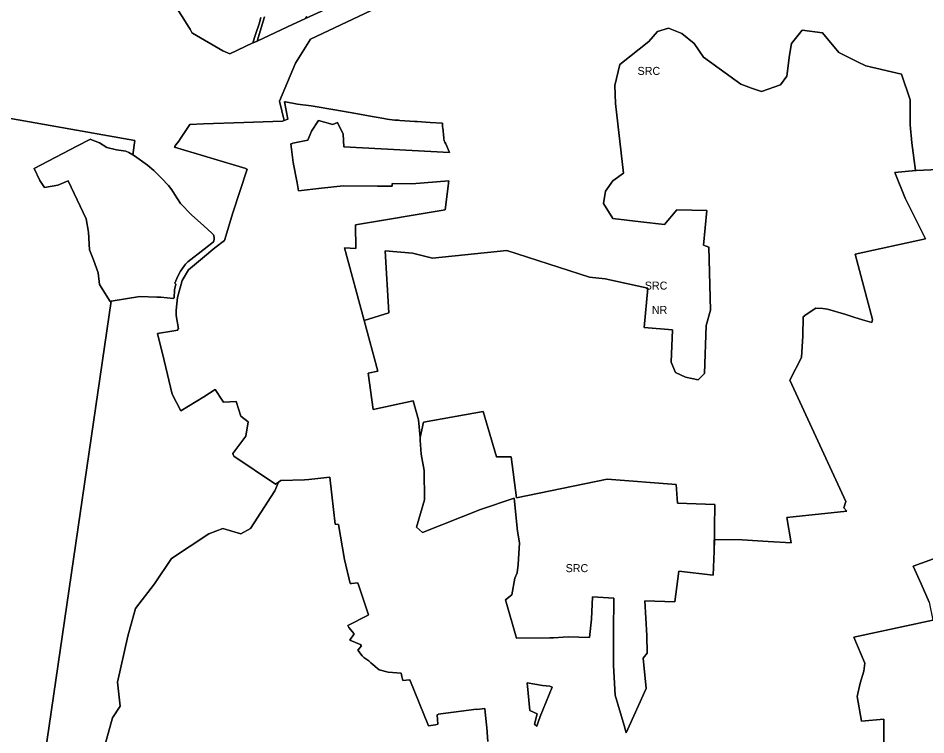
# Model space of a CAD drawing. Extents: x 598968 to 613553, y 4409678 to 4430833.
# Drawn here: x 605292 to 606653, y 4414204 to 4415278 of the extents above; entities that cross this region are included whole.
import ezdxf

# ---------------------------------------------------------------- set-up
doc = ezdxf.new("R2010")
doc.units = 0
for name, color, linetype in [('1', 7, 'Continuous'), ('Nucli Rural', 7, 'Continuous'), ('Sòl Rústic Comú', 7, 'Continuous')]:
    doc.layers.add(name, color=color, linetype=linetype)

msp = doc.modelspace()

# ---------------------------------------------------------------- linework, layer by layer
at = {"layer": '1'}
for points in [[(605525.6972, 4415299.6089), (605547.7802, 4415264.6209), (605549.5351, 4415261.4135), (605552.5806, 4415255.6474), (605553.1532, 4415255.3186), (605598.7444, 4415229.1359), (605609.1856, 4415224.6552), (605643.5975, 4415240.7757), (605643.8664, 4415240.9011), (605643.8703, 4415240.9026), (605647.8489, 4415253.402), (605649.7389, 4415259.3394), (605651.5659, 4415265.0792), (605653.0331, 4415269.498), (605655.7911, 4415279.0062)], [(605661.1567, 4415279.7497), (605649.9412, 4415243.7057), (605649.9455, 4415243.7077), (605695.5427, 4415264.7584), (605722.5347, 4415277.5027), (605724.6022, 4415280.4167)], [(605724.6022, 4415280.4167), (605722.5347, 4415277.5027), (605722.6392, 4415277.2668), (605752.1398, 4415290.8862)], [(605655.7911, 4415279.0062), (605653.0331, 4415269.498), (605651.5659, 4415265.0792), (605649.7389, 4415259.3394), (605647.8489, 4415253.402), (605643.8703, 4415240.9026), (605643.8744, 4415240.9036), (605649.9412, 4415243.7057), (605661.1567, 4415279.7497)]]:
    msp.add_lwpolyline(points, dxfattribs=at)
for points in [[(605463.4611, 4415073.426), (605457.6411, 4415076.8972), (605453.0401, 4415078.5902), (605439.3201, 4415080.8702), (605424.8201, 4415084.3902), (605413.9101, 4415091.2402), (605400.9731, 4415096.0988), (605400.0191, 4415096.4572), (605379.7631, 4415086.0116), (605315.6501, 4415052.9502), (605324.1501, 4415034.7302), (605331.2801, 4415024.2702), (605351.2001, 4415027.8102), (605366.7701, 4415034.3302), (605393.6601, 4414977.2102), (605397.0701, 4414957.3602), (605398.9701, 4414931.0202), (605404.9301, 4414916.0202), (605411.8401, 4414896.2502), (605413.8501, 4414879.0402), (605429.6851, 4414853.6892), (605431.4065, 4414853.9728), (605474.1001, 4414861.0102), (605499.7201, 4414860.0402), (605505.6601, 4414859.9602), (605524.9001, 4414857.9902), (605525.6501, 4414859.2302), (605526.1301, 4414871.0602), (605528.2501, 4414879.4502), (605526.6801, 4414880.7902), (605531.1501, 4414891.5802), (605535.3801, 4414898.9402), (605542.6701, 4414909.3802), (605546.2101, 4414913.0202), (605570.5901, 4414931.9702), (605584.4601, 4414943.0702), (605585.7501, 4414946.4102), (605585.6701, 4414950.0002), (605584.4301, 4414953.5302), (605582.1801, 4414956.1202), (605570.3701, 4414966.6202), (605551.8301, 4414983.2602), (605535.3301, 4415000.4502), (605525.9901, 4415014.4902), (605521.9401, 4415020.7502), (605517.1301, 4415027.1662), (605506.1101, 4415038.9402), (605495.1301, 4415049.6602), (605485.8361, 4415057.5072), (605466.1201, 4415071.8402)], [(606071.5501, 4414223.5502), (606074.3301, 4414231.8802), (606092.5201, 4414275.7002), (606089.1301, 4414277.5502), (606077.7201, 4414278.4802), (606054.9001, 4414282.4902), (606054.9007, 4414282.483), (606058.8301, 4414240.7602), (606069.7701, 4414236.0002), (606065.8301, 4414220.4602), (606069.4981, 4414217.5852), (606069.5301, 4414217.5602)]]:
    msp.add_lwpolyline(points, close=True, dxfattribs=at)
at = {"layer": 'Nucli Rural'}
for points in [[(606693.3797, 4415052.3558), (606638.0967, 4415049.5824), (606637.3409, 4415049.5444), (606637.1065, 4415049.5246), (606605.9285, 4415046.8728), (606621.5387, 4415008.4928), (606652.2685, 4414947.2428), (606546.5985, 4414924.3728), (606572.8787, 4414826.3628), (606571.6341, 4414822.0776), (606557.8605, 4414826.252), (606544.7307, 4414830.2314), (606532.6505, 4414833.8926), (606505.2609, 4414842.194), (606497.9985, 4414842.8428), (606487.5107, 4414843.694), (606473.3141, 4414833.9804), (606468.5105, 4414830.6938), (606468.1087, 4414802.0928), (606466.0087, 4414769.5528), (606448.6985, 4414735.6128), (606532.8087, 4414553.883), (606529.4585, 4414544.4728), (606534.2705, 4414539.2988), (606444.2271, 4414529.9412), (606450.9747, 4414491.9956), (606416.4197, 4414493.7786), (606377.1385, 4414496.4596), (606336.6027, 4414496.846), (606335.8865, 4414496.8528), (606335.8121, 4414496.8534), (606335.7715, 4414496.8538), (606335.1373, 4414479.4628), (606333.8287, 4414443.5718), (606282.1287, 4414449.8028), (606276.4985, 4414403.5428), (606231.5087, 4414405.0328), (606234.1911, 4414353.2728), (606235.0385, 4414326.9128), (606228.8687, 4414319.1228), (606233.3785, 4414274.0028), (606203.2781, 4414207.5304), (606200.3241, 4414218.2812), (606186.6285, 4414264.0328), (606184.5787, 4414308.3328), (606184.2999, 4414359.2928), (606184.9175, 4414409.2052), (606153.1187, 4414411.323), (606151.5687, 4414377.8928), (606148.5619, 4414350.247), (606116.3987, 4414350.9628), (606094.2487, 4414349.8928), (606088.6787, 4414349.9028), (606038.7285, 4414349.43), (606022.5487, 4414406.6728), (606032.1505, 4414413.875), (606036.5887, 4414438.9628), (606039.9287, 4414446.9328), (606041.5823, 4414459.5922), (606043.2287, 4414491.7828), (606040.3331, 4414509.2934), (606035.2393, 4414558.9848), (605984.8103, 4414541.8184), (605898.0385, 4414507.6628), (605888.8487, 4414515.5828), (605901.2187, 4414556.5828), (605900.4985, 4414600.1628), (605896.1387, 4414624.5928), (605894.6285, 4414645.9828), (605894.3123, 4414649.8836), (605894.3095, 4414649.9182), (605892.1801, 4414676.172), (605884.0767, 4414704.6982), (605824.1087, 4414691.883), (605816.3187, 4414746.0848), (605830.8101, 4414749.008), (605810.3427, 4414825.2124), (605810.3385, 4414825.2278), (605781.1847, 4414933.7734), (605798.1787, 4414932.979), (605797.4785, 4414968.1628), (605931.9987, 4414990.7628), (605937.5769, 4415034.5134), (605881.8833, 4415029.8164), (605852.4341, 4415030.5174), (605852.4341, 4415026.3106), (605830.6979, 4415026.3106), (605779.1619, 4415026.661), (605746.7409, 4415023.4546), (605711.8977, 4415019.4344), (605710.2043, 4415031.2868), (605703.8935, 4415061.611), (605700.3529, 4415089.7802), (605703.1073, 4415090.2152), (605703.0851, 4415090.4674), (605703.7863, 4415090.4674), (605725.8731, 4415095.3756), (605731.4825, 4415108.6978), (605742.0001, 4415124.825), (605763.7363, 4415118.8648), (605770.3973, 4415121.6694), (605778.8113, 4415104.1402), (605780.2139, 4415085.2088), (605938.3115, 4415076.8028), (605932.7985, 4415089.5728), (605931.5087, 4415091.9828), (605930.4787, 4415094.4128), (605930.0587, 4415097.0728), (605929.7885, 4415099.7128), (605929.5487, 4415102.2428), (605929.3087, 4415104.823), (605929.0687, 4415107.4628), (605928.7987, 4415109.9928), (605928.4485, 4415112.6528), (605928.0187, 4415115.4628), (605927.7787, 4415120.7628), (605909.5987, 4415121.8428), (605890.0687, 4415122.9028), (605886.6687, 4415123.0928), (605863.9087, 4415124.7928), (605862.2587, 4415124.9128), (605859.3687, 4415125.133), (605856.4387, 4415125.2428), (605848.5185, 4415126.343), (605845.1885, 4415126.803), (605839.8087, 4415127.7828), (605828.6685, 4415129.8028), (605822.5487, 4415130.6928), (605798.0485, 4415135.3728), (605766.3387, 4415140.7628), (605730.9387, 4415146.473), (605710.5687, 4415149.2328), (605692.3585, 4415152.5328), (605691.0087, 4415152.6628), (605696.0687, 4415126.4828), (605690.6147, 4415124.531), (605690.4161, 4415124.46), (605690.3481, 4415124.4356), (605689.2785, 4415124.053), (605688.1287, 4415123.8928), (605630.3687, 4415121.4228), (605569.5553, 4415119.4668), (605549.2187, 4415118.8128), (605547.9387, 4415117.0128), (605534.9285, 4415097.8028), (605532.5587, 4415093.7128), (605528.2487, 4415088.0128), (605526.4687, 4415085.6728), (605525.9789, 4415084.634), (605633.2475, 4415052.7316), (605633.1339, 4415052.35), (605635.3187, 4415051.7728), (605613.5165, 4414986.4824), (605601.1685, 4414945.0228), (605586.4215, 4414933.8314), (605568.0585, 4414918.6028), (605547.3785, 4414900.9128), (605537.6887, 4414885.1428), (605530.7187, 4414859.4428), (605528.6067, 4414840.5814), (605528.4385, 4414832.4728), (605532.0653, 4414812.6308), (605530.9693, 4414812.4686), (605531.2187, 4414810.7628), (605525.3031, 4414809.7196), (605500.7685, 4414805.3928), (605510.4757, 4414765.129), (605522.7275, 4414714.6274), (605535.5729, 4414689.8052), (605570.0157, 4414710.5376), (605587.3085, 4414721.8128), (605597.6091, 4414705.5496), (605599.4523, 4414702.809), (605618.5187, 4414703.9626), (605625.5391, 4414681.6952), (605636.5285, 4414673.3328), (605632.9287, 4414651.9128), (605613.6787, 4414625.7628), (605614.6455, 4414622.9674), (605615.3487, 4414621.6828), (605677.5985, 4414579.7726), (605682.2393, 4414582.9346), (605685.5239, 4414585.1726), (605721.2701, 4414586.2738), (605727.7313, 4414586.8794), (605758.8993, 4414590.439), (605761.8515, 4414563.6808), (605767.0237, 4414520.1392), (605772.1387, 4414519.2726), (605781.2621, 4414466.9284), (605789.3189, 4414431.3308), (605791.5421, 4414431.2096), (605800.7985, 4414432.0128), (605801.2339, 4414430.6814), (605801.3887, 4414430.6728), (605817.2387, 4414383.9428), (605816.6061, 4414383.6628), (605816.6487, 4414383.5326), (605785.9085, 4414368.3728), (605787.6525, 4414365.4314), (605795.3087, 4414355.8628), (605789.1207, 4414346.2872), (605806.0887, 4414339.073), (605805.2085, 4414338.3578), (605806.6787, 4414337.7328), (605801.0591, 4414331.0036), (605807.7187, 4414322.7428), (605810.0239, 4414320.2708), (605817.7487, 4414315.1728), (605820.3985, 4414312.1428), (605832.8587, 4414301.823), (605846.4387, 4414298.2328), (605865.9987, 4414297.0228), (605866.9361, 4414291.6356), (605868.3633, 4414285.9152), (605878.9385, 4414286.9728), (605906.9087, 4414217.9526), (605917.5985, 4414219.633), (605921.1935, 4414220.2478), (605920.1577, 4414234.5092), (605921.7101, 4414234.7122), (605921.7085, 4414235.2228), (605979.1887, 4414242.9028), (605979.4131, 4414242.2612), (605991.5857, 4414243.8536), (605992.5605, 4414233.3226), (605994.2599, 4414214.967), (605996.1683, 4414194.3536)], [(606657.6687, 4414402.8928), (606645.7887, 4414430.633), (606633.6009, 4414457.23), (606676.4087, 4414472.4428)], [(606589.6085, 4414156.6828), (606589.4585, 4414228.0228), (606556.3885, 4414224.9728), (606549.7685, 4414261.7928), (606554.4285, 4414281.6828), (606559.5585, 4414299.8628), (606561.1087, 4414311.6728), (606544.7987, 4414350.8186), (606663.3687, 4414376.3228)]]:
    msp.add_lwpolyline(points, dxfattribs=at)
msp.add_lwpolyline([(606071.5501, 4414223.5502), (606069.5301, 4414217.5602), (606069.4981, 4414217.5852), (606065.8301, 4414220.4602), (606069.7701, 4414236.0002), (606058.8301, 4414240.7602), (606054.9007, 4414282.483), (606054.9001, 4414282.4902), (606077.7201, 4414278.4802), (606089.1301, 4414277.5502), (606092.5201, 4414275.7002), (606074.3301, 4414231.8802)], close=True, dxfattribs=at)
at = {"layer": 'Sòl Rústic Comú'}
for points in [[(605414.0375, 4414161.6918), (605433.1629, 4414229.6918), (605444.6631, 4414247.192), (605440.8507, 4414283.192), (605456.2885, 4414352.192), (605467.6013, 4414393.692), (605496.3517, 4414430.6922), (605521.8521, 4414468.6922), (605577.7905, 4414505.6924), (605598.5407, 4414513.6924), (605625.6659, 4414505.6924), (605640.0411, 4414513.6924), (605676.7291, 4414569.6926), (605682.2393, 4414582.9346), (605677.5985, 4414579.7726), (605615.3487, 4414621.6828), (605614.6455, 4414622.9674), (605613.6787, 4414625.7628), (605632.9287, 4414651.9128), (605636.5285, 4414673.3328), (605625.5391, 4414681.6952), (605618.5187, 4414703.9626), (605599.4523, 4414702.809), (605597.6091, 4414705.5496), (605587.3085, 4414721.8128), (605570.0157, 4414710.5376), (605535.5729, 4414689.8052), (605522.7275, 4414714.6274), (605510.4757, 4414765.129), (605500.7685, 4414805.3928), (605525.3031, 4414809.7196), (605531.2187, 4414810.7628), (605530.9693, 4414812.4686), (605532.0653, 4414812.6308), (605528.4385, 4414832.4728), (605528.6067, 4414840.5814), (605530.7187, 4414859.4428), (605537.6887, 4414885.1428), (605547.3785, 4414900.9128), (605568.0585, 4414918.6028), (605586.4215, 4414933.8314), (605601.1685, 4414945.0228), (605613.5165, 4414986.4824), (605635.3187, 4415051.7728), (605633.1339, 4415052.35), (605633.2475, 4415052.7316), (605525.9789, 4415084.634), (605526.4687, 4415085.6728), (605528.2487, 4415088.0128), (605532.5587, 4415093.7128), (605534.9285, 4415097.8028), (605547.9387, 4415117.0128), (605549.2187, 4415118.8128), (605569.5553, 4415119.4668), (605630.3687, 4415121.4228), (605688.1287, 4415123.8928), (605689.2785, 4415124.053), (605690.3481, 4415124.4356), (605690.4161, 4415124.46), (605690.3959, 4415124.5282), (605683.5439, 4415153.693), (605707.7945, 4415210.6932), (605729.9823, 4415246.6932), (605910.7971, 4415332.1936)], [(605910.7971, 4415332.1936), (605729.9823, 4415246.6932), (605707.7945, 4415210.6932), (605683.5439, 4415153.693), (605690.3959, 4415124.5282), (605690.4161, 4415124.46), (605690.6147, 4415124.531), (605696.0687, 4415126.4828), (605691.0087, 4415152.6628), (605692.3585, 4415152.5328), (605710.5687, 4415149.2328), (605730.9387, 4415146.473), (605766.3387, 4415140.7628), (605798.0485, 4415135.3728), (605822.5487, 4415130.6928), (605828.6685, 4415129.8028), (605839.8087, 4415127.7828), (605845.1885, 4415126.803), (605848.5185, 4415126.343), (605856.4387, 4415125.2428), (605859.3687, 4415125.133), (605862.2587, 4415124.9128), (605863.9087, 4415124.7928), (605886.6687, 4415123.0928), (605890.0687, 4415122.9028), (605909.5987, 4415121.8428), (605927.7787, 4415120.7628), (605928.0187, 4415115.4628), (605928.4485, 4415112.6528), (605928.7987, 4415109.9928), (605929.0687, 4415107.4628), (605929.3087, 4415104.823), (605929.5487, 4415102.2428), (605929.7885, 4415099.7128), (605930.0587, 4415097.0728), (605930.4787, 4415094.4128), (605931.5087, 4415091.9828), (605932.7985, 4415089.5728), (605938.3115, 4415076.8028), (605780.2139, 4415085.2088), (605778.8113, 4415104.1402), (605770.3973, 4415121.6694), (605763.7363, 4415118.8648), (605742.0001, 4415124.825), (605731.4825, 4415108.6978), (605725.8731, 4415095.3756), (605703.7863, 4415090.4674), (605703.0851, 4415090.4674), (605703.1073, 4415090.2152), (605700.3529, 4415089.7802), (605703.8935, 4415061.611), (605710.2043, 4415031.2868), (605711.8977, 4415019.4344), (605746.7409, 4415023.4546), (605779.1619, 4415026.661), (605830.6979, 4415026.3106), (605852.4341, 4415026.3106), (605852.4341, 4415030.5174), (605881.8833, 4415029.8164), (605937.5769, 4415034.5134), (605931.9987, 4414990.7628), (605797.4785, 4414968.1628), (605798.1787, 4414932.979), (605781.1847, 4414933.7734), (605810.3385, 4414825.2278), (605810.4831, 4414825.2514), (605847.5445, 4414836.693), (605841.8573, 4414929.193), (605883.2327, 4414925.6932), (605913.2329, 4414918.1932), (606024.2341, 4414929.6934), (606148.2353, 4414890.1934), (606171.7355, 4414887.6936), (606235.7987, 4414873.6936), (606230.1109, 4414814.6936), (606273.0489, 4414811.1936), (606270.6111, 4414762.6936), (606277.1111, 4414747.1936), (606292.5487, 4414740.1936), (606311.1739, 4414736.1936), (606320.8615, 4414745.6936), (606323.2993, 4414817.6936), (606329.7995, 4414840.6936), (606327.3623, 4414934.6938), (606319.2997, 4414937.6938), (606324.1125, 4414989.6938), (606279.5495, 4414990.6938), (606260.9243, 4414968.6938), (606225.2365, 4414972.6936), (606183.1111, 4414977.6936), (606169.2985, 4415000.1936), (606172.5485, 4415018.6936), (606183.1113, 4415034.1936), (606199.2989, 4415045.6936), (606187.1743, 4415150.1938), (606186.3619, 4415177.1938), (606193.6745, 4415208.6938), (606237.3001, 4415243.194), (606250.4877, 4415258.194), (606266.6755, 4415263.194), (606286.9257, 4415255.194), (606305.1757, 4415240.194), (606319.3633, 4415219.694), (606375.1137, 4415179.194), (606391.3015, 4415173.194), (606406.4891, 4415168.194), (606434.8643, 4415178.1942), (606443.9895, 4415191.1942), (606448.0523, 4415222.6942), (606451.0523, 4415240.1942), (606467.3025, 4415260.1942), (606497.6779, 4415256.1944), (606521.9905, 4415226.6944), (606550.3657, 4415212.6944), (606562.5533, 4415206.6944), (606616.2413, 4415194.1944), (606629.3663, 4415155.6944), (606629.3661, 4415118.1944), (606631.4287, 4415091.1944), (606637.0909, 4415049.6314), (606637.1065, 4415049.5246), (606637.3409, 4415049.5444), (606638.0967, 4415049.5824), (606693.3797, 4415052.3558)], [(605752.1398, 4415290.8862), (605722.6392, 4415277.2668), (605722.5347, 4415277.5027), (605695.5427, 4415264.7584), (605649.9455, 4415243.7077), (605649.9412, 4415243.7057), (605643.8744, 4415240.9036), (605643.8703, 4415240.9026), (605643.8664, 4415240.9011), (605643.5975, 4415240.7757), (605609.1856, 4415224.6552), (605598.7444, 4415229.1359), (605553.1532, 4415255.3186), (605552.5806, 4415255.6474), (605549.5351, 4415261.4135), (605547.7802, 4415264.6209), (605525.6972, 4415299.6089)], [(605023.4055, 4415173.103), (605466.5523, 4415094.5888), (605463.4611, 4415073.426), (605466.1201, 4415071.8402), (605485.8361, 4415057.5072), (605495.1301, 4415049.6602), (605506.1101, 4415038.9402), (605517.1301, 4415027.1662), (605521.9401, 4415020.7502), (605525.9901, 4415014.4902), (605535.3301, 4415000.4502), (605551.8301, 4414983.2602), (605570.3701, 4414966.6202), (605582.1801, 4414956.1202), (605584.4301, 4414953.5302), (605585.6701, 4414950.0002), (605585.7501, 4414946.4102), (605584.4601, 4414943.0702), (605570.5901, 4414931.9702), (605546.2101, 4414913.0202), (605542.6701, 4414909.3802), (605535.3801, 4414898.9402), (605531.1501, 4414891.5802), (605526.6801, 4414880.7902), (605528.2501, 4414879.4502), (605526.1301, 4414871.0602), (605525.6501, 4414859.2302), (605524.9001, 4414857.9902), (605505.6601, 4414859.9602), (605499.7201, 4414860.0402), (605474.1001, 4414861.0102), (605431.4065, 4414853.9728), (605328.5131, 4414149.5416)], [(605328.5131, 4414149.5416), (605431.4065, 4414853.9728), (605429.6851, 4414853.6892), (605413.8501, 4414879.0402), (605411.8401, 4414896.2502), (605404.9301, 4414916.0202), (605398.9701, 4414931.0202), (605397.0701, 4414957.3602), (605393.6601, 4414977.2102), (605366.7701, 4415034.3302), (605351.2001, 4415027.8102), (605331.2801, 4415024.2702), (605324.1501, 4415034.7302), (605315.6501, 4415052.9502), (605379.7631, 4415086.0116), (605400.0191, 4415096.4572), (605400.9731, 4415096.0988), (605413.9101, 4415091.2402), (605424.8201, 4415084.3902), (605439.3201, 4415080.8702), (605453.0401, 4415078.5902), (605457.6411, 4415076.8972), (605463.4611, 4415073.426), (605466.5523, 4415094.5888), (605023.4055, 4415173.103)], [(605996.1683, 4414194.3536), (605994.2599, 4414214.967), (605992.5605, 4414233.3226), (605991.5857, 4414243.8536), (605979.4131, 4414242.2612), (605979.1887, 4414242.9028), (605921.7085, 4414235.2228), (605921.7101, 4414234.7122), (605920.1577, 4414234.5092), (605921.1935, 4414220.2478), (605917.5985, 4414219.633), (605906.9087, 4414217.9526), (605878.9385, 4414286.9728), (605868.3633, 4414285.9152), (605866.9361, 4414291.6356), (605865.9987, 4414297.0228), (605846.4387, 4414298.2328), (605832.8587, 4414301.823), (605820.3985, 4414312.1428), (605817.7487, 4414315.1728), (605810.0239, 4414320.2708), (605807.7187, 4414322.7428), (605801.0591, 4414331.0036), (605806.6787, 4414337.7328), (605805.2085, 4414338.3578), (605806.0887, 4414339.073), (605789.1207, 4414346.2872), (605795.3087, 4414355.8628), (605787.6525, 4414365.4314), (605785.9085, 4414368.3728), (605816.6487, 4414383.5326), (605816.6061, 4414383.6628), (605817.2387, 4414383.9428), (605801.3887, 4414430.6728), (605801.2339, 4414430.6814), (605800.7985, 4414432.0128), (605791.5421, 4414431.2096), (605789.3189, 4414431.3308), (605781.2621, 4414466.9284), (605772.1387, 4414519.2726), (605767.0237, 4414520.1392), (605761.8515, 4414563.6808), (605758.8993, 4414590.439), (605727.7313, 4414586.8794), (605721.2701, 4414586.2738), (605685.5239, 4414585.1726), (605682.2393, 4414582.9346), (605676.7291, 4414569.6926), (605640.0411, 4414513.6924), (605625.6659, 4414505.6924), (605598.5407, 4414513.6924), (605577.7905, 4414505.6924), (605521.8521, 4414468.6922), (605496.3517, 4414430.6922), (605467.6013, 4414393.692), (605456.2885, 4414352.192), (605440.8507, 4414283.192), (605444.6631, 4414247.192), (605433.1629, 4414229.6918), (605414.0375, 4414161.6918)], [(606755.9265, 4414166.6936), (606805.4273, 4414249.6938), (606864.4907, 4414359.694), (606850.1161, 4414462.194), (606718.1725, 4414483.8358), (606717.9931, 4414484.0276), (606718.1119, 4414483.4172), (606722.7387, 4414459.6628), (606687.3291, 4414446.1214), (606676.4087, 4414472.4428), (606633.6009, 4414457.23), (606645.7887, 4414430.633), (606657.6687, 4414402.8928), (606663.3687, 4414376.3228), (606544.7987, 4414350.8186), (606561.1087, 4414311.6728), (606559.5585, 4414299.8628), (606554.4285, 4414281.6828), (606549.7685, 4414261.7928), (606556.3885, 4414224.9728), (606589.4585, 4414228.0228), (606589.6085, 4414156.6828)]]:
    msp.add_lwpolyline(points, dxfattribs=at)
for points in [[(606637.1065, 4415049.5246), (606637.0909, 4415049.6314), (606631.4287, 4415091.1944), (606629.3661, 4415118.1944), (606629.3663, 4415155.6944), (606616.2413, 4415194.1944), (606562.5533, 4415206.6944), (606550.3657, 4415212.6944), (606521.9905, 4415226.6944), (606497.6779, 4415256.1944), (606467.3025, 4415260.1942), (606451.0523, 4415240.1942), (606448.0523, 4415222.6942), (606443.9895, 4415191.1942), (606434.8643, 4415178.1942), (606406.4891, 4415168.194), (606391.3015, 4415173.194), (606375.1137, 4415179.194), (606319.3633, 4415219.694), (606305.1757, 4415240.194), (606286.9257, 4415255.194), (606266.6755, 4415263.194), (606250.4877, 4415258.194), (606237.3001, 4415243.194), (606193.6745, 4415208.6938), (606186.3619, 4415177.1938), (606187.1743, 4415150.1938), (606199.2989, 4415045.6936), (606183.1113, 4415034.1936), (606172.5485, 4415018.6936), (606169.2985, 4415000.1936), (606183.1111, 4414977.6936), (606225.2365, 4414972.6936), (606260.9243, 4414968.6938), (606279.5495, 4414990.6938), (606324.1125, 4414989.6938), (606319.2997, 4414937.6938), (606327.3623, 4414934.6938), (606329.7995, 4414840.6936), (606323.2993, 4414817.6936), (606320.8615, 4414745.6936), (606311.1739, 4414736.1936), (606292.5487, 4414740.1936), (606277.1111, 4414747.1936), (606270.6111, 4414762.6936), (606273.0489, 4414811.1936), (606230.1109, 4414814.6936), (606235.7987, 4414873.6936), (606171.7355, 4414887.6936), (606148.2353, 4414890.1934), (606024.2341, 4414929.6934), (605913.2329, 4414918.1932), (605883.2327, 4414925.6932), (605841.8573, 4414929.193), (605847.5445, 4414836.693), (605810.4831, 4414825.2514), (605810.3385, 4414825.2278), (605810.3427, 4414825.2124), (605830.8101, 4414749.008), (605816.3187, 4414746.0848), (605824.1087, 4414691.883), (605884.0767, 4414704.6982), (605892.1801, 4414676.172), (605894.3095, 4414649.9182), (605894.3123, 4414649.8836), (605894.4317, 4414650.0008), (605899.2945, 4414672.693), (605989.1079, 4414688.693), (606009.0453, 4414620.693), (606031.0455, 4414620.693), (606038.9829, 4414559.193), (606174.7345, 4414587.1932), (606278.4855, 4414579.1934), (606280.4855, 4414551.1934), (606336.3609, 4414549.1934), (606335.1373, 4414479.4628), (606335.7715, 4414496.8538), (606335.8121, 4414496.8534), (606335.8865, 4414496.8528), (606336.6027, 4414496.846), (606377.1385, 4414496.4596), (606416.4197, 4414493.7786), (606450.9747, 4414491.9956), (606444.2271, 4414529.9412), (606534.2705, 4414539.2988), (606529.4585, 4414544.4728), (606532.8087, 4414553.883), (606448.6985, 4414735.6128), (606466.0087, 4414769.5528), (606468.1087, 4414802.0928), (606468.5105, 4414830.6938), (606473.3141, 4414833.9804), (606487.5107, 4414843.694), (606497.9985, 4414842.8428), (606505.2609, 4414842.194), (606532.6505, 4414833.8926), (606544.7307, 4414830.2314), (606557.8605, 4414826.252), (606571.6341, 4414822.0776), (606572.8787, 4414826.3628), (606546.5985, 4414924.3728), (606652.2685, 4414947.2428), (606621.5387, 4415008.4928), (606605.9285, 4415046.8728)], [(606335.1373, 4414479.4628), (606336.3609, 4414549.1934), (606280.4855, 4414551.1934), (606278.4855, 4414579.1934), (606174.7345, 4414587.1932), (606038.9829, 4414559.193), (606031.0455, 4414620.693), (606009.0453, 4414620.693), (605989.1079, 4414688.693), (605899.2945, 4414672.693), (605894.4317, 4414650.0008), (605894.3123, 4414649.8836), (605894.6285, 4414645.9828), (605896.1387, 4414624.5928), (605900.4985, 4414600.1628), (605901.2187, 4414556.5828), (605888.8487, 4414515.5828), (605898.0385, 4414507.6628), (605984.8103, 4414541.8184), (606035.2393, 4414558.9848), (606040.3331, 4414509.2934), (606043.2287, 4414491.7828), (606041.5823, 4414459.5922), (606039.9287, 4414446.9328), (606036.5887, 4414438.9628), (606032.1505, 4414413.875), (606022.5487, 4414406.6728), (606038.7285, 4414349.43), (606088.6787, 4414349.9028), (606094.2487, 4414349.8928), (606116.3987, 4414350.9628), (606148.5619, 4414350.247), (606151.5687, 4414377.8928), (606153.1187, 4414411.323), (606184.9175, 4414409.2052), (606184.2999, 4414359.2928), (606184.5787, 4414308.3328), (606186.6285, 4414264.0328), (606200.3241, 4414218.2812), (606203.2781, 4414207.5304), (606233.3785, 4414274.0028), (606228.8687, 4414319.1228), (606235.0385, 4414326.9128), (606234.1911, 4414353.2728), (606231.5087, 4414405.0328), (606276.4985, 4414403.5428), (606282.1287, 4414449.8028), (606333.8287, 4414443.5718)]]:
    msp.add_lwpolyline(points, close=True, dxfattribs=at)

# ---------------------------------------------------------------- texts
at = {"layer": 'Nucli Rural'}
msp.add_text('NR', height=12, dxfattribs=at).set_placement((606241.8557, 4414834.8653))
at = {"layer": 'Sòl Rústic Comú'}
for p in [(606220.4567, 4415192.9442), (606231.3035, 4414871.3284), (606112.6048, 4414448.1117)]:
    msp.add_text('SRC', height=12, dxfattribs=at).set_placement(p)

doc.saveas('drawing.dxf')
